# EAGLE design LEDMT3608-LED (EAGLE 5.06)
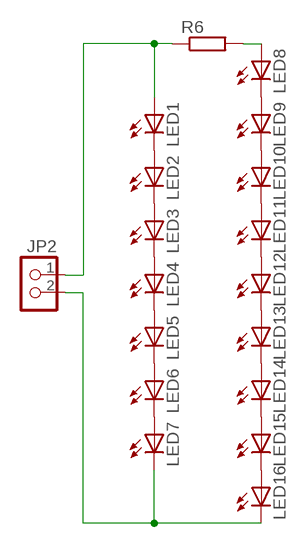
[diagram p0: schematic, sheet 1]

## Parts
JP2  PINHD-1X2  [1X02]
LED1  LED2835W  [LED_2835W]
LED2  LED2835W  [LED_2835W]
LED3  LED2835W  [LED_2835W]
LED4  LED2835W  [LED_2835W]
LED5  LED2835W  [LED_2835W]
LED6  LED2835W  [LED_2835W]
LED7  LED2835W  [LED_2835W]
LED8  LED2835W  [LED_2835W]
LED9  LED2835W  [LED_2835W]
LED10  LED2835W  [LED_2835W]
LED11  LED2835W  [LED_2835W]
LED12  LED2835W  [LED_2835W]
LED13  LED2835W  [LED_2835W]
LED14  LED2835W  [LED_2835W]
LED15  LED2835W  [LED_2835W]
LED16  LED2835W  [LED_2835W]
R6  REZISTOR_SMD1206_KEMET_REFLOW  [C1206K]

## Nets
N$1: LED1.K(C) LED2.A
N$2: LED2.K(C) LED3.A
N$3: LED3.K(C) LED4.A
N$4: LED4.K(C) LED5.A
N$5: LED5.K(C) LED6.A
N$6: LED6.K(C) LED7.A
N$7: LED8.K(C) LED9.A
N$8: LED9.K(C) LED10.A
N$9: LED10.K(C) LED11.A
N$10: LED11.K(C) LED12.A
N$11: LED12.K(C) LED13.A
N$12: LED13.K(C) LED14.A
N$13: LED14.K(C) LED15.A
N$14: LED15.K(C) LED16.A
N$15: LED8.A R6.2
N$32: JP2.1 LED1.A R6.1
N$33: JP2.2 LED7.K(C) LED16.K(C)

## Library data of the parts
JP2 = #bcs_pinhead:PINHD-1X2: PIN HEADER
LED1-LED16 = #bcs7d:LED: LED
R6 = #bcs7d:REZISTOR_

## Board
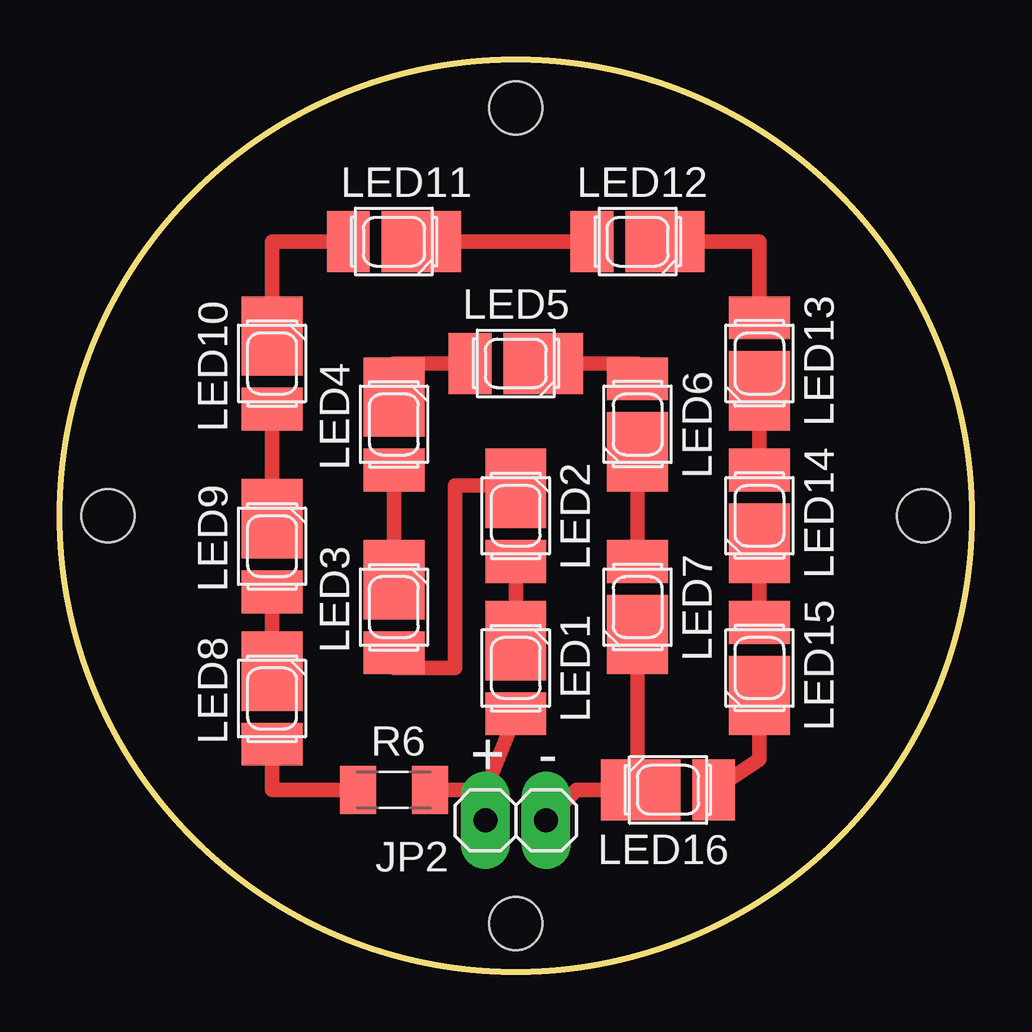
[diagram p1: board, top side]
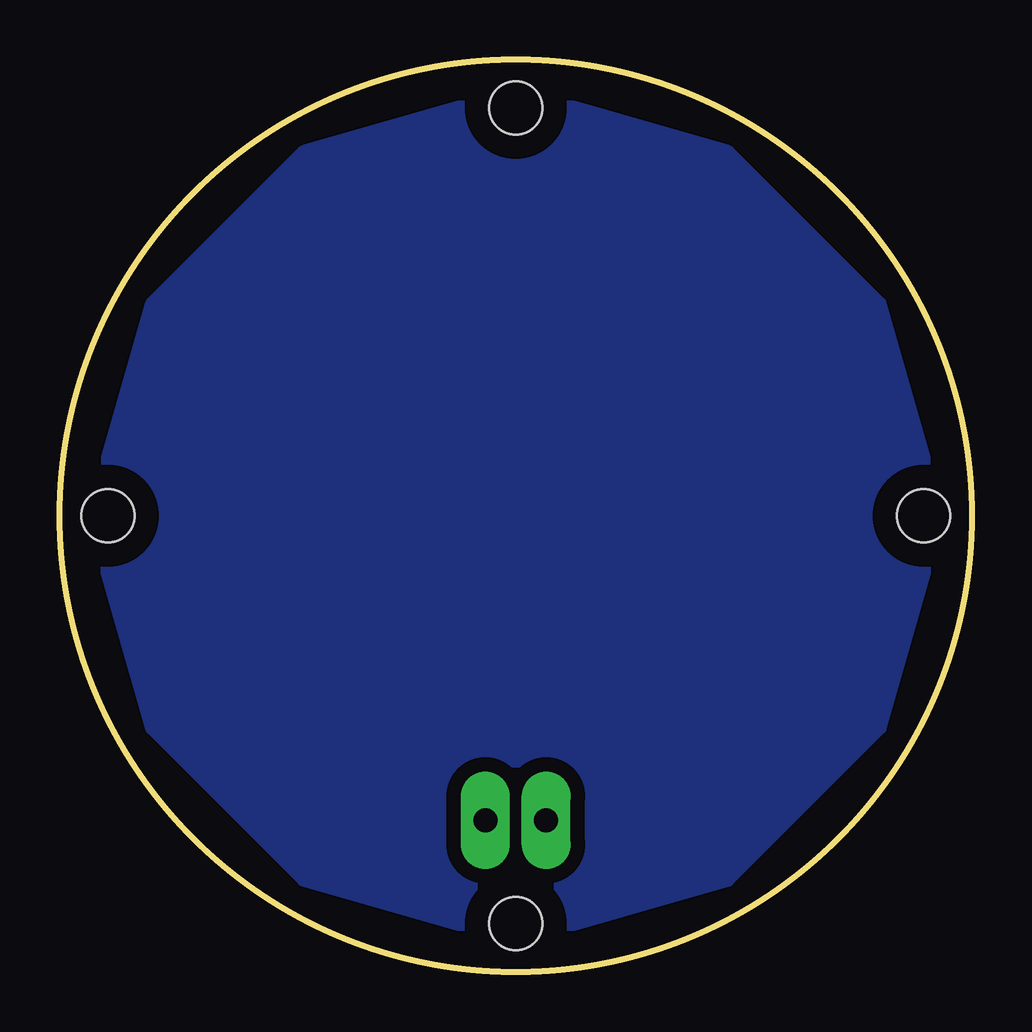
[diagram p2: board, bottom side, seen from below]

Size 38 x 38 mm. Coordinates in mm from the lower left corner, seen from the top.
Outline: circle at 19,19 radius 19
Copper layers (1*16): Top 0.035mm / dielectric 1.5mm / Bottom 0.035mm
Design rules "default": minimum track width 10mil, minimum drill 24mil, track to track 8mil, track to pad 8mil, pad to pad 8mil, via to via 8mil, smd to smd 8mil, copper to edge 40mil, drill to drill 8mil, minimum pad ring 10mil, minimum via ring 8mil, stop-mask expansion 4mil, vias tented up to drill 0mil, thermal gap 10mil
Holes 2.2 mm at 36,19 2,19 19,36 19,2

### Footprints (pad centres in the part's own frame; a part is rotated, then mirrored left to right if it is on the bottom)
1X02 = drill 1 pad 2.032 long: 1 -1.27,0; 2 1.27,0
LED_2835W = smd 1.778 x 2.54: A -1.905,0 | smd 3.302 x 2.54: K 1.143,0
C1206K = smd 1.5 x 2: 1 -1.5,0; 2 1.5,0

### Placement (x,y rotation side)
JP2  19,6.3 0 top
LED1  19,12.65 90 top
LED2  19,19 90 top
LED3  13.92,15.19 90 top
LED4  13.92,22.81 90 top
LED5  19,25.35 0 top
LED6  24.08,22.81 270 top
LED7  24.08,15.19 270 top
LED8  8.84,11.38 90 top
LED9  8.84,17.73 90 top
LED10  8.84,25.35 90 top
LED11  13.92,30.43 0 top
LED12  24.08,30.43 0 top
LED13  29.16,25.35 270 top
LED14  29.16,19 270 top
LED15  29.16,12.65 270 top
LED16  25.35,7.57 180 top
R6  13.92,7.57 180 top

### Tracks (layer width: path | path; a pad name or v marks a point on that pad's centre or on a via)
N$1
  Top 0.61: LED2.A LED1.K
N$2
  Top 0.61: LED2.K 19,20.27 16.46,20.27 16.46,12.65 13.92,12.65 LED3.A
N$3
  Top 0.61: LED4.A LED3.K
N$4
  Top 0.61: LED4.K 13.92,25.35 LED5.A
N$5
  Top 0.61: 19,25.35 LED5.K 24.08,25.35 LED6.A
N$6
  Top 0.61: LED7.A LED6.K
N$7
  Top 0.61: LED9.A LED8.K
N$8
  Top 0.61: LED10.A LED9.K
N$9
  Top 0.61: LED10.K 8.84,30.43 LED11.A
N$10
  Top 0.61: LED11.K LED12.A
N$11
  Top 0.61: LED12.K 29.16,30.43 LED13.A
N$12
  Top 0.61: LED14.A LED13.K
N$13
  Top 0.61: LED15.A LED14.K
N$14
  Top 0.61: LED15.K 29.16,8.84 LED16.A
N$15
  Top 0.61: R6.2 8.84,7.57 LED8.A
N$31
  pour Bottom (isolate 0.61): 1.22,19 3.76,27.89 10.11,34.24 19,36.78 27.89,34.24 34.24,27.89 36.78,19 34.24,10.11 27.89,3.76 19,1.22 10.11,3.76 3.76,10.11
N$32
  Top 0.61: LED1.A 17.73,7.57 | 17.73,7.57 JP2.1 | 17.73,7.57 R6.1
N$33
  Top 0.61: LED7.K 24.08,7.57 | 24.08,7.57 21.54,7.57 JP2.2 | 24.08,7.57 LED16.K

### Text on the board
tNames: + -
